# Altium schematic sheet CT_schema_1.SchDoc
size 582 x 258 mm
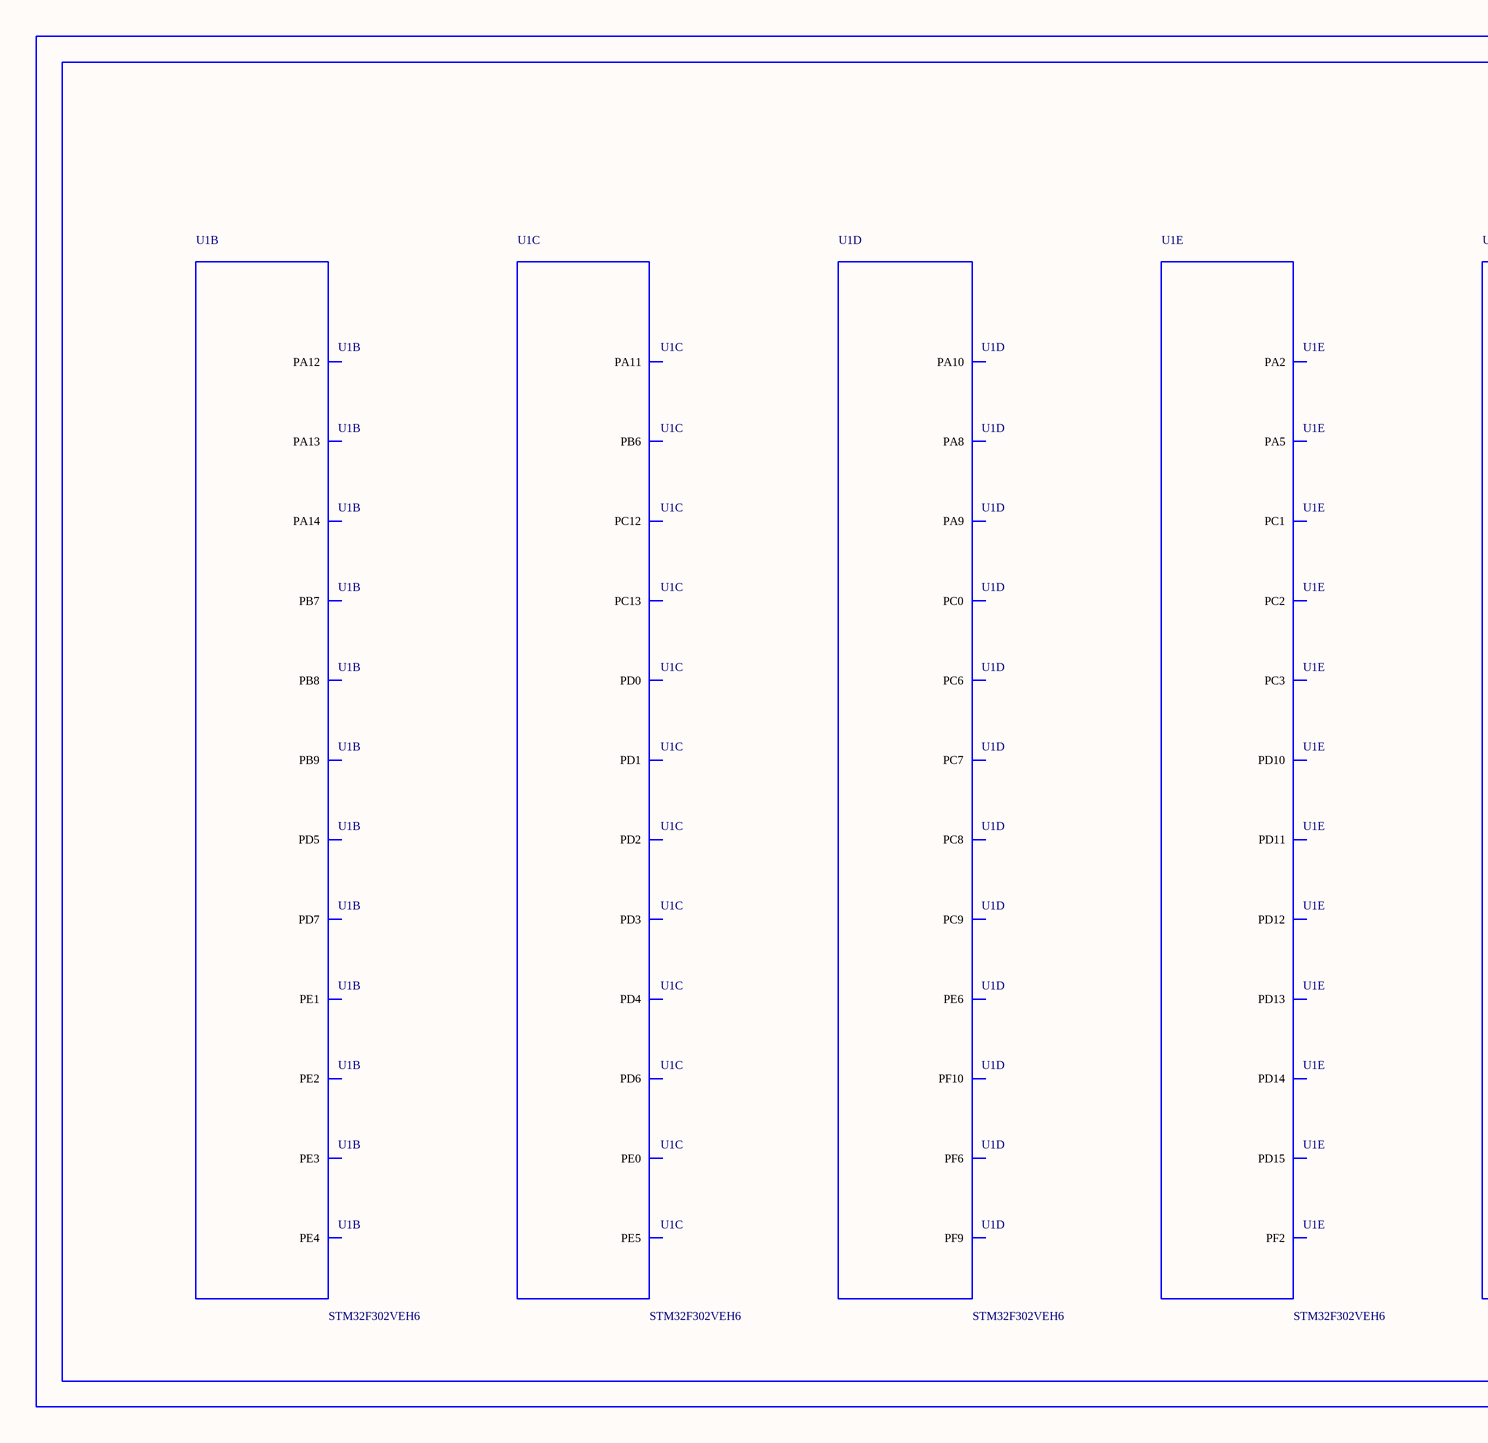
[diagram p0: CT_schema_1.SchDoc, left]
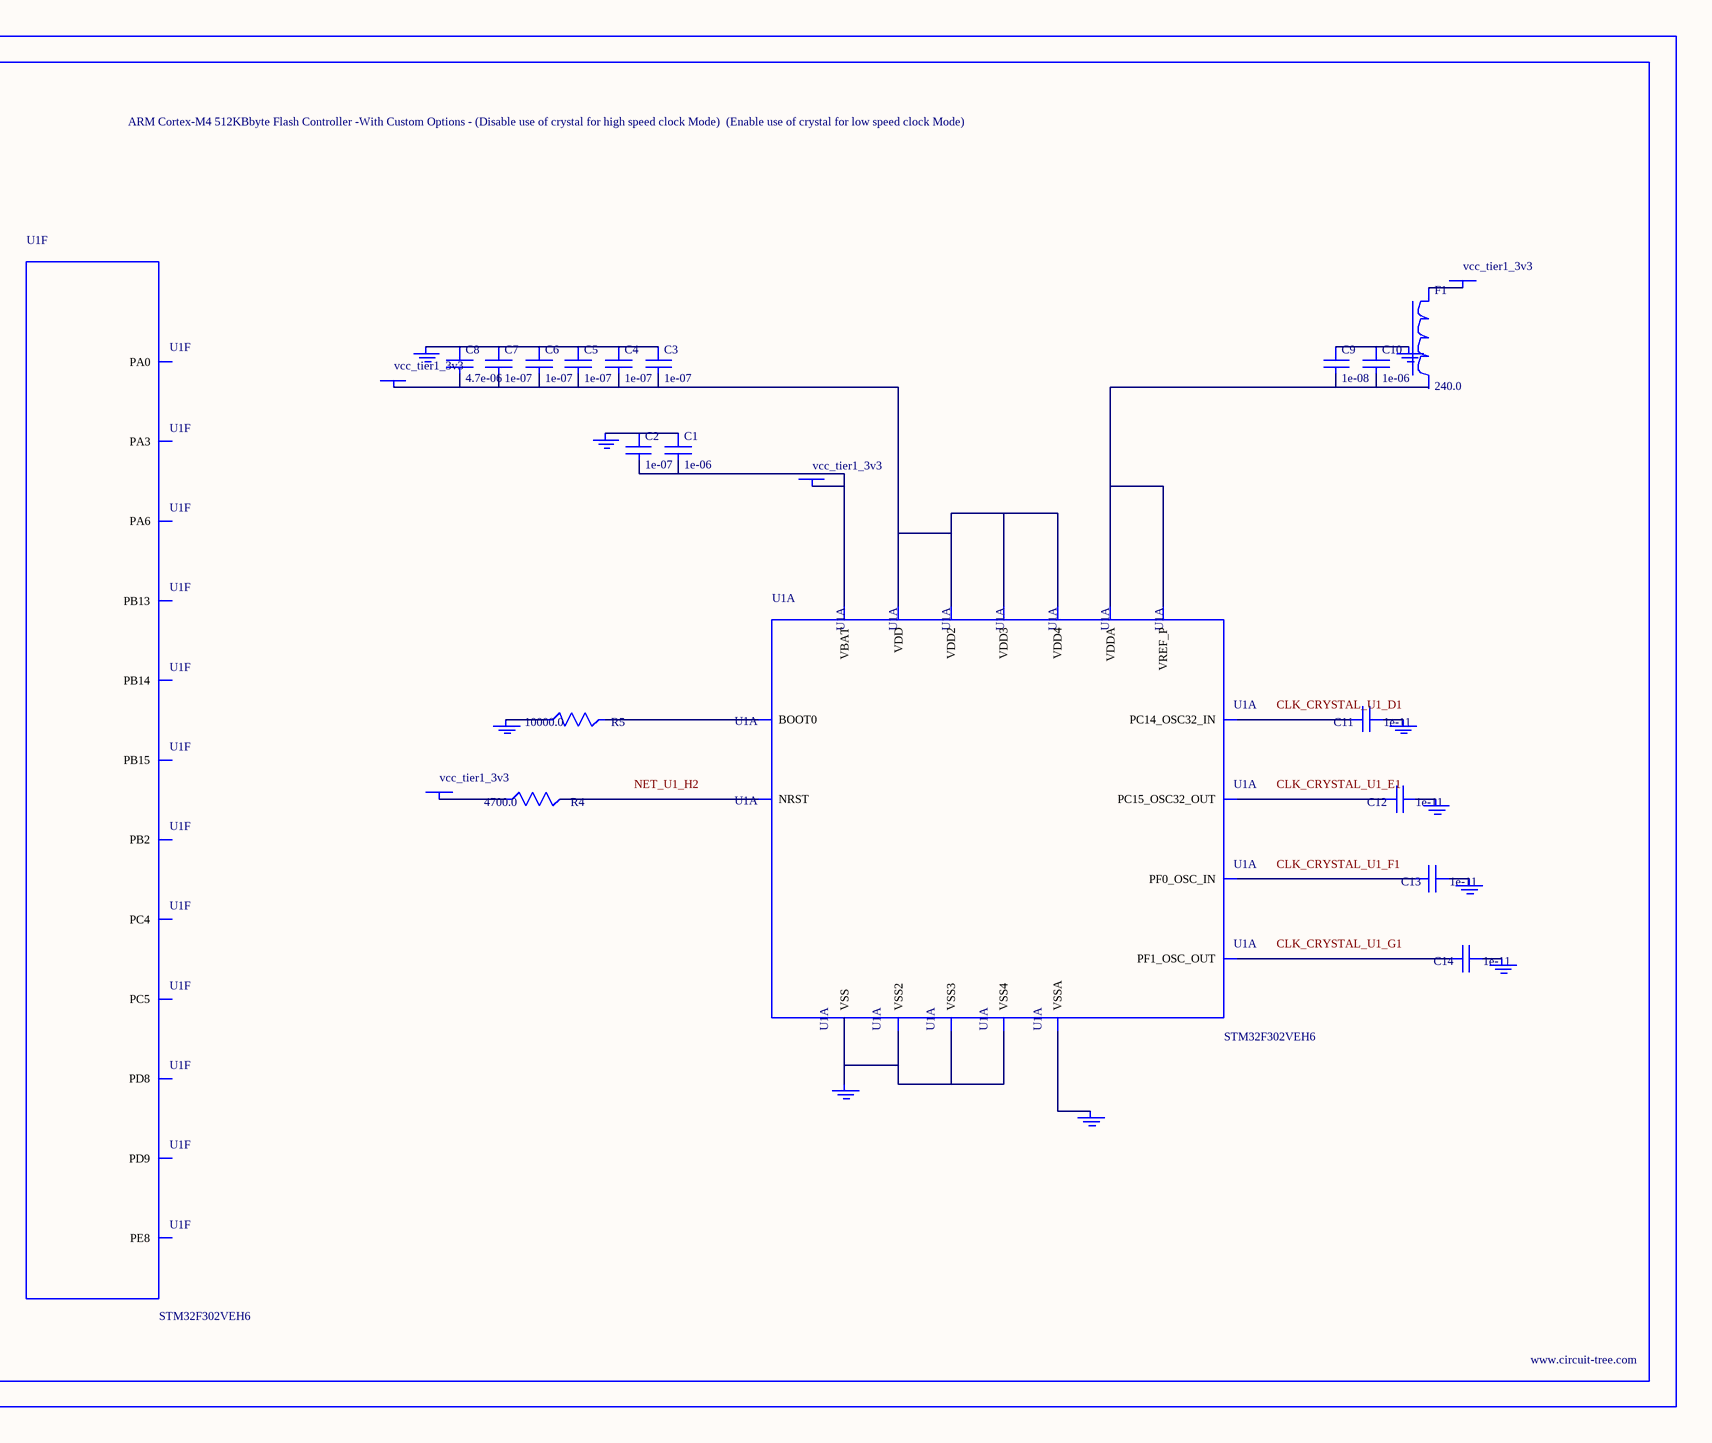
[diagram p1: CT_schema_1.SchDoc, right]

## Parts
BORDER0  (no value)
C1  1e-06  [C0603]
C2  1e-07  [C0603]
C3  1e-07  [C0603]
C4  1e-07  [C0603]
C5  1e-07  [C0603]
C6  1e-07  [C0603]
C7  1e-07  [C0603]
C8  4.7e-06  [C0603]
C9  1e-08  [C0603]
C10  1e-06  [C0603]
C11  1e-11  [C0402]
C12  1e-11  [C0402]
C13  1e-11  [C0402]
C14  1e-11  [C0402]
F1  240.0  [L0603]
GND_INSTANCE_0_0  (no value)
GND_INSTANCE_0_1  (no value)
GND_INSTANCE_0_2  (no value)
GND_INSTANCE_0_3  (no value)
GND_INSTANCE_0_4  (no value)
GND_INSTANCE_0_5  (no value)
GND_INSTANCE_0_6  (no value)
GND_INSTANCE_0_7  (no value)
GND_INSTANCE_0_8  (no value)
GND_INSTANCE_0_9  (no value)
POWER_INSTANCE_0_0  vcc_tier1_3v3
POWER_INSTANCE_0_1  vcc_tier1_3v3
POWER_INSTANCE_0_2  vcc_tier1_3v3
POWER_INSTANCE_0_3  vcc_tier1_3v3
R4  4700.0  [R0603]
R5  10000.0  [R0603]
U1  STM32F302VEH6  [UFBGA100]  (parts A,B,C,D,E,F of 9)

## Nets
NetC1_1: C1.1 C2.1 GND_INSTANCE_0_0.0(GND)
NetC1_2: C1.2 C2.2 POWER_INSTANCE_0_0.0(PWR) U1.E2(VBAT)
NetC3_1: C3.1 C4.1 C5.1 C6.1 C7.1 C8.1 GND_INSTANCE_0_2.0(GND)
NetC3_2: C3.2 C4.2 C5.2 C6.2 C7.2 C8.2 POWER_INSTANCE_0_2.0(PWR) U1.C4(VDD) U1.G11(VDD2) U1.G12(VDD3) U1.H3(VDD4)
NetC9_1: C9.1 C10.1 GND_INSTANCE_0_1.0(GND)
NetC9_2: C9.2 C10.2 U1.L1(VDDA) U1.M1(VREF_P)
NetC11_1: C11.1 GND_INSTANCE_0_4.0(GND)
NetC11_2: C11.2 U1.D1(PC14_OSC32_IN)
NetC12_1: C12.1 GND_INSTANCE_0_5.0(GND)
NetC12_2: C12.2 U1.E1(PC15_OSC32_OUT)
NetC13_1: C13.1 GND_INSTANCE_0_6.0(GND)
NetC13_2: C13.2 U1.F1(PF0_OSC_IN)
NetC14_1: C14.1 GND_INSTANCE_0_7.0(GND)
NetC14_2: C14.2 U1.G1(PF1_OSC_OUT)
NetF1_1: F1.1 POWER_INSTANCE_0_1.0(PWR)
NetGND_INSTANCE_0_3_0: GND_INSTANCE_0_3.0(GND) R5.1
NetGND_INSTANCE_0_8_0: GND_INSTANCE_0_8.0(GND) U1.K1(VSSA)
NetGND_INSTANCE_0_9_0: GND_INSTANCE_0_9.0(GND) U1.D3(VSS) U1.E3(VSS2) U1.F11(VSS3) U1.F12(VSS4)
NetPOWER_INSTANCE_0_3_0: POWER_INSTANCE_0_3.0(PWR) R4.1
NetR4_2: R4.2 U1.H2(NRST)
NetR5_2: R5.2 U1.A4(BOOT0)

Not connected (* = marked no-connect by the designer): F1 2; U1 A1(PE3) A2(PE1) A3(PB8) A5(PD7) A6(PD5) A10(PA14) A11(PA13) A12(PA12) B1(PE4) B2(PE2) B3(PB9) B4(PB7) B5(PB6) B6(PD6) B7(PD4) B8(PD3) B9(PD1) B10(PC12) B12(PA11) C1(PC13) C2(PE5) C3(PE0) C8(PD2) C9(PD0) C11(PF6) C12(PA10) D2(PE6) D10(PA9) D11(PA8) D12(PC9) E10(PC8) E11(PC7) E12(PC6) F2(PF9) G2(PF10) H1(PC0) H10(PD15) H11(PD14) H12(PD13) J1(PF2) J2(PC1) J3(PC2) J10(PD12) J11(PD11) J12(PD10) K2(PC3) K3(PA2) K4(PA5) K5(PC4) K8(PD9) K9(PD8) K10(PB15) K11(PB14) K12(PB13) L2(PA0) L3(PA3) L4(PA6) L5(PC5) L6(PB2) L7(PE8)

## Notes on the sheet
- Labels drawn without touching a wire or pin: CLK_CRYSTAL_U1_D1, CLK_CRYSTAL_U1_E1, CLK_CRYSTAL_U1_F1, CLK_CRYSTAL_U1_G1, NET_U1_H2

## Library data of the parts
BORDER0 = BORDER_PAGE0
C1 C10 = C0603C105K3RACTU
C2-C7 = 06035C104K4Z2A
C8 = GRM188R6YA475KE15D
C9 = 06035C103K4Z2A
C11-C14 = C0402C100K3GACTU
F1 = Z0603C241ASMST
GND_INSTANCE_0_0-GND_INSTANCE_0_9 = GND
POWER_INSTANCE_0_0-POWER_INSTANCE_0_3 = PWR
R4 = RC0603JR-074K7L
R5 = RC0603JR-0710KL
